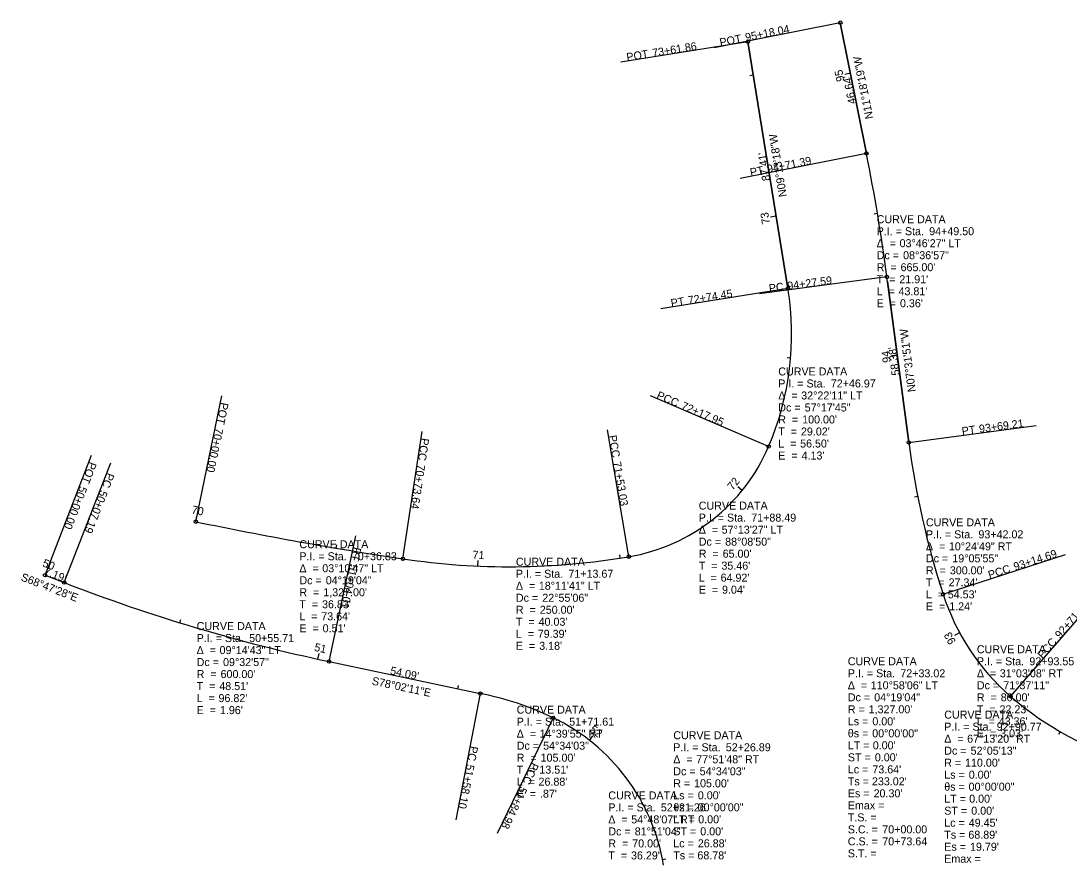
# Model space of a CAD drawing. Extents: x 2047391 to 2047982, y 456752 to 457262.
# Drawn here: x 2047391.4 to 2047758.1, y 456967.1 to 457261.6 of the extents above; entities that cross this region are included whole.
import ezdxf

# ---------------------------------------------------------------- set-up
doc = ezdxf.new("R2010")
doc.units = 0
for name, color, linetype in [('GE_P_Alignment', 7, 'Continuous'), ('GE_P_Alignment_100_Bearings', 7, 'Continuous'), ('GE_P_Alignment_100_Cardinal_Points', 7, 'Continuous'), ('GE_P_Alignment_100_Curve_Data', 7, 'Continuous'), ('GE_P_Alignment_100_Distances', 7, 'Continuous'), ('GE_P_Alignment_100_Stations', 7, 'Continuous')]:
    doc.layers.add(name, color=color, linetype=linetype)

msp = doc.modelspace()

# ---------------------------------------------------------------- linework, layer by layer
at = {"layer": 'GE_P_Alignment'}
for p, q in [((2047678.1, 457261.03), (2047687.24, 457215.29)), ((2047687.24, 457215.29), (2047678.1, 457261.03)), ((2047645.77, 457254.37), (2047659.78, 457168.09)), ((2047659.78, 457168.09), (2047645.77, 457254.37)), ((2047702.06, 457114.21), (2047694.41, 457172.08)), ((2047694.63, 457170.44), (2047702.06, 457114.21)), ((2047399.84, 457067.77), (2047406.55, 457065.16)), ((2047499.24, 457037.56), (2047552.15, 457026.34))]:
    msp.add_line(p, q, dxfattribs=at)
for centre, radius, start, end in [((2047035.15, 457084.92), 665, 7.53092, 11.30514), ((2047035.15, 457084.92), 665, 7.53092, 11.30514), ((2047561.07, 457152.07), 100, 336.8518, 9.2216), ((2047561.07, 457152.07), 100, 336.8518, 9.2216), ((2047593.25, 457138.31), 65, 279.6276, 336.8518), ((2047593.25, 457138.31), 65, 279.6276, 336.8518), ((2047999.47, 457153.53), 300, 187.5309, 197.9445), ((2047999.47, 457153.53), 300, 187.5309, 197.9445), ((2047722.75, 458385.68), 1327, 258.25334, 261.43295), ((2047722.75, 458385.68), 1327, 258.25334, 261.43295), ((2047562.31, 457320.7), 250, 261.433, 279.6276), ((2047562.31, 457320.7), 250, 261.433, 279.6276), ((2047623.61, 457624.52), 600, 248.79098, 258.03635), ((2047790.18, 457085.75), 80, 197.9445, 228.9967), ((2047790.18, 457085.75), 80, 197.9445, 228.9967), ((2047532.02, 456923.29), 105, 64.2811, 78.9463), ((2047809.86, 457108.39), 110, 228.9967, 254.7532), ((2047809.86, 457108.39), 110, 228.9967, 254.7532), ((2047547.24, 456954.81), 70, 9.5095, 64.3115)]:
    msp.add_arc(centre, radius, start, end, dxfattribs=at)
at = {"layer": 'GE_P_Alignment_100_Cardinal_Points'}
for p, q in [((2047678.1, 457261.03), (2047633.97, 457252.2)), ((2047645.77, 457254.37), (2047601.35, 457247.16)), ((2047687.24, 457215.29), (2047643.12, 457206.47)), ((2047694.41, 457172.08), (2047649.8, 457166.18)), ((2047659.78, 457168.09), (2047615.36, 457160.88)), ((2047452.59, 457086.47), (2047461.75, 457130.53)), ((2047653.02, 457112.75), (2047611.64, 457130.44)), ((2047702.06, 457114.21), (2047746.67, 457120.11)), ((2047525.07, 457073.49), (2047531.77, 457117.99)), ((2047604.12, 457074.22), (2047596.6, 457118.59)), ((2047399.84, 457067.77), (2047416.12, 457109.72)), ((2047406.55, 457065.16), (2047422.83, 457107.11)), ((2047499.24, 457037.56), (2047508.56, 457081.58)), ((2047714.07, 457061.1), (2047756.88, 457074.96)), ((2047737.69, 457025.37), (2047767.21, 457059.33)), ((2047552.15, 457026.34), (2047543.52, 456982.18)), ((2047577.59, 457017.89), (2047558.08, 456977.34))]:
    msp.add_line(p, q, dxfattribs=at)
for centre in [(2047678.1, 457261.03), (2047645.77, 457254.37), (2047687.24, 457215.29), (2047694.41, 457172.08), (2047659.78, 457168.09), (2047653.02, 457112.75), (2047702.06, 457114.21), (2047452.59, 457086.47), (2047525.07, 457073.49), (2047604.12, 457074.22), (2047399.84, 457067.77), (2047406.55, 457065.16), (2047714.07, 457061.1), (2047499.24, 457037.56), (2047552.15, 457026.34), (2047737.69, 457025.37), (2047577.59, 457017.89)]:
    msp.add_circle(centre, 0.6, dxfattribs=at)
at = {"layer": 'GE_P_Alignment_100_Stations'}
for p, q in [((2047647.67, 457242.67), (2047646.48, 457242.48)), ((2047681.64, 457243.34), (2047679.67, 457242.95)), ((2047655.68, 457193.31), (2047653.71, 457192.99)), ((2047691.1, 457194.25), (2047689.92, 457194.05)), ((2047660.72, 457143.72), (2047659.52, 457143.82)), ((2047698.03, 457144.73), (2047696.04, 457144.47)), ((2047643.79, 457097.43), (2047642.23, 457098.68)), ((2047705.19, 457095.26), (2047704.01, 457095.02)), ((2047452.59, 457086.47), (2047453, 457088.43)), ((2047501.72, 457077.22), (2047501.92, 457078.4)), ((2047551.29, 457070.94), (2047551.38, 457072.94)), ((2047601.13, 457073.73), (2047600.94, 457074.92)), ((2047399.84, 457067.77), (2047400.56, 457069.63)), ((2047446.97, 457051.11), (2047447.33, 457052.26)), ((2047719.84, 457047.62), (2047718.09, 457046.67)), ((2047495.31, 457038.4), (2047495.74, 457040.35)), ((2047544.23, 457028.02), (2047544.47, 457029.2)), ((2047590.32, 457009.98), (2047591.55, 457011.56)), ((2047755.03, 457013.02), (2047754.44, 457011.98)), ((2047615.93, 456968.27), (2047617.11, 456968.5))]:
    msp.add_line(p, q, dxfattribs=at)

# ---------------------------------------------------------------- texts
at = {"layer": 'GE_P_Alignment_100_Bearings'}
for s, rotation, p in [('N11°18\'19"W', 101.3051, (2047689.68, 457227.61)), ('N09°13\'18"W', 99.2216, (2047659.41, 457200.29)), ('N07°31\'51"W', 97.5309, (2047704.55, 457132.01)), ('S68°47\'28"E', 338.791, (2047391.13, 457066)), ('S78°02\'11"E', 348.0363, (2047514.01, 457029.52))]:
    msp.add_text(s, height=2.8, rotation=rotation, dxfattribs=at).set_placement(p)
at = {"layer": 'GE_P_Alignment_100_Cardinal_Points'}
for s, rotation, p in [('95+18.04', 11.3051, (2047645.12, 457254.48)), ('POT', 11.3051, (2047636.17, 457252.69)), ('73+61.86', 9.2216, (2047612.53, 457249.02)), ('POT', 9.2216, (2047603.52, 457247.56)), ('94+71.39', 11.3051, (2047652.76, 457208.44)), ('PT', 11.3051, (2047646.79, 457207.25)), ('94+27.59', 7.5309, (2047659.77, 457167.55)), ('72+74.45', 9.2216, (2047625.03, 457162.5)), ('PC', 7.5309, (2047653.3, 457166.69)), ('PT', 9.2216, (2047619.02, 457161.52)), ('PCC', 336.8518, (2047613.58, 457129.67)), ('POT', 258.2533, (2047461.35, 457128.36)), ('72+17.95', 336.8518, (2047622.17, 457125.99)), ('PT', 7.5309, (2047720.79, 457116.73)), ('93+69.21', 7.5309, (2047726.82, 457117.53)), ('70+00.00', 258.2533, (2047459.49, 457119.42)), ('PCC', 279.6276, (2047597, 457116.51)), ('PCC', 261.433, (2047531.5, 457115.86)), ('POT', 248.791, (2047415.37, 457107.64)), ('70+73.64', 261.433, (2047530.11, 457106.62)), ('71+53.03', 279.6276, (2047598.56, 457107.29)), ('PC', 248.791, (2047421.59, 457103.8)), ('50+00.00', 248.791, (2047412.06, 457099.13)), ('50+07.19', 248.791, (2047419.23, 457097.72)), ('PT', 258.0363, (2047507.8, 457077.75)), ('93+14.69', 17.9445, (2047739.24, 457069.3)), ('51+04.01', 258.0363, (2047506.54, 457071.8)), ('PCC', 17.9445, (2047730.35, 457066.42)), ('92+71.33', 48.9967, (2047755.01, 457045.37)), ('PCC', 48.9967, (2047748.88, 457038.32)), ('PC', 258.9463, (2047548.65, 457008.17)), ('51+58.10', 258.9463, (2047547.4, 457001.76)), ('PCC', 244.3115, (2047570.21, 457002.46)), ('51+84.98', 244.3115, (2047566.16, 456994.03))]:
    msp.add_text(s, height=2.8, rotation=rotation, dxfattribs=at).set_placement(p)
at = {"layer": 'GE_P_Alignment_100_Curve_Data'}
for s, p in [('CURVE DATA', (2047690.83, 457190.88)), ('P.I. = Sta. ', (2047690.83, 457186.68)), ('94+49.50', (2047709.2, 457186.68)), ('Δ  = ', (2047690.83, 457182.48)), ('03°46\'27" LT', (2047698.85, 457182.48)), ('Dc = ', (2047690.83, 457178.28)), ('08°36\'57"', (2047700.07, 457178.28)), ('R  = ', (2047690.83, 457174.08)), ("665.00'", (2047699.19, 457174.08)), ('T  = ', (2047690.83, 457169.88)), ("21.91'", (2047698.76, 457169.88)), ('L  = ', (2047690.83, 457165.68)), ("43.81'", (2047698.47, 457165.68)), ('E  = ', (2047690.83, 457161.48)), ("0.36'", (2047698.98, 457161.48)), ('CURVE DATA', (2047656.4, 457137.62)), ('P.I. = Sta. ', (2047656.4, 457133.42)), ('72+46.97', (2047674.77, 457133.42)), ('Δ  = ', (2047656.4, 457129.22)), ('32°22\'11" LT', (2047664.42, 457129.22)), ('Dc = ', (2047656.4, 457125.02)), ('57°17\'45"', (2047665.64, 457125.02)), ('R  = ', (2047656.4, 457120.82)), ("100.00'", (2047664.76, 457120.82)), ('T  = ', (2047656.4, 457116.62)), ("29.02'", (2047664.33, 457116.62)), ('L  = ', (2047656.4, 457112.42)), ("56.50'", (2047664.04, 457112.42)), ('E  = ', (2047656.4, 457108.22)), ("4.13'", (2047664.55, 457108.22)), ('CURVE DATA', (2047628.57, 457090.69)), ('P.I. = Sta. ', (2047628.57, 457086.49)), ('71+88.49', (2047646.94, 457086.49)), ('CURVE DATA', (2047708.06, 457084.85)), ('Δ  = ', (2047628.57, 457082.29)), ('57°13\'27" LT', (2047636.59, 457082.29)), ('P.I. = Sta. ', (2047708.06, 457080.65)), ('93+42.02', (2047726.43, 457080.65)), ('CURVE DATA', (2047488.83, 457077.18)), ('Dc = ', (2047628.57, 457078.09)), ('88°08\'50"', (2047637.81, 457078.09)), ('P.I. = Sta. ', (2047488.83, 457072.98)), ('70+36.83', (2047507.2, 457072.98)), ('R  = ', (2047628.57, 457073.89)), ("65.00'", (2047636.94, 457073.89)), ('Δ  = ', (2047708.06, 457076.45)), ('10°24\'49" RT', (2047716.09, 457076.45)), ('CURVE DATA', (2047564.59, 457071.06)), ('T  = ', (2047628.57, 457069.69)), ("35.46'", (2047636.5, 457069.69)), ('Dc = ', (2047708.06, 457072.25)), ('19°05\'55"', (2047717.3, 457072.25)), ('Δ  = ', (2047488.83, 457068.78)), ('03°10\'47" LT', (2047496.85, 457068.78)), ('P.I. = Sta. ', (2047564.59, 457066.86)), ('71+13.67', (2047582.96, 457066.86)), ('R  = ', (2047708.06, 457068.05)), ("300.00'", (2047716.43, 457068.05)), ('Dc = ', (2047488.83, 457064.58)), ('04°19\'04"', (2047498.07, 457064.58)), ('Δ  = ', (2047564.59, 457062.66)), ('18°11\'41" LT', (2047572.62, 457062.66)), ('L  = ', (2047628.57, 457065.49)), ("64.92'", (2047636.22, 457065.49)), ('T  = ', (2047708.06, 457063.85)), ("27.34'", (2047716, 457063.85)), ('R  = ', (2047488.83, 457060.38)), ("1,327.00'", (2047497.2, 457060.38)), ('Dc = ', (2047564.59, 457058.46)), ('22°55\'06"', (2047573.83, 457058.46)), ('E  = ', (2047628.57, 457061.29)), ("9.04'", (2047636.72, 457061.29)), ('L  = ', (2047708.06, 457059.65)), ("54.53'", (2047715.71, 457059.65)), ('T  = ', (2047488.83, 457056.18)), ("36.83'", (2047496.76, 457056.18)), ('E  = ', (2047708.06, 457055.45)), ("1.24'", (2047716.22, 457055.45)), ('L  = ', (2047488.83, 457051.98)), ("73.64'", (2047496.48, 457051.98)), ('R  = ', (2047564.59, 457054.26)), ("250.00'", (2047572.96, 457054.26)), ('CURVE DATA', (2047452.89, 457048.56)), ('E  = ', (2047488.83, 457047.78)), ("0.51'", (2047496.98, 457047.78)), ('T  = ', (2047564.59, 457050.06)), ("40.03'", (2047572.53, 457050.06)), ('P.I. = Sta. ', (2047452.89, 457044.36)), ('50+55.71', (2047471.26, 457044.36)), ('L  = ', (2047564.59, 457045.86)), ("79.39'", (2047572.24, 457045.86)), ('Δ  = ', (2047452.89, 457040.16)), ('09°14\'43" LT', (2047460.91, 457040.16)), ('E  = ', (2047564.59, 457041.66)), ("3.18'", (2047572.75, 457041.66)), ('CURVE DATA', (2047725.88, 457040.44)), ('Dc = ', (2047452.89, 457035.96)), ('09°32\'57"', (2047462.13, 457035.96)), ('CURVE DATA', (2047680.73, 457036.24)), ('P.I. = Sta. ', (2047725.88, 457036.24)), ('92+93.55', (2047744.25, 457036.24)), ('R  = ', (2047452.89, 457031.76)), ("600.00'", (2047461.26, 457031.76)), ('P.I. = Sta. ', (2047680.73, 457032.04)), ('72+33.02', (2047699.1, 457032.04)), ('Δ  = ', (2047725.88, 457032.04)), ('31°03\'08" RT', (2047733.9, 457032.04)), ('T  = ', (2047452.89, 457027.56)), ("48.51'", (2047460.82, 457027.56)), ('Δ  = ', (2047680.73, 457027.84)), ('110°58\'06" LT', (2047688.75, 457027.84)), ('Dc = ', (2047725.88, 457027.84)), ('71°37\'11"', (2047735.12, 457027.84)), ('L  = ', (2047452.89, 457023.36)), ("96.82'", (2047460.54, 457023.36)), ('Dc = ', (2047680.73, 457023.64)), ('04°19\'04"', (2047689.97, 457023.64)), ('R  = ', (2047725.88, 457023.64)), ("80.00'", (2047734.24, 457023.64)), ('E  = ', (2047452.89, 457019.16)), ("1.96'", (2047461.04, 457019.16)), ('CURVE DATA', (2047564.87, 457019.32)), ('R = ', (2047680.73, 457019.44)), ("1,327.00'", (2047688.01, 457019.44)), ('T  = ', (2047725.88, 457019.44)), ("22.23'", (2047733.81, 457019.44)), ('P.I. = Sta. ', (2047564.87, 457015.12)), ('51+71.61', (2047583.24, 457015.12)), ('Ls = ', (2047680.73, 457015.24)), ("0.00'", (2047689.32, 457015.24)), ('CURVE DATA', (2047714.47, 457017.57)), ('L  = ', (2047725.88, 457015.24)), ("43.36'", (2047733.52, 457015.24)), ('Δ  = ', (2047564.87, 457010.92)), ('14°39\'55" RT', (2047572.89, 457010.92)), ('θs = ', (2047680.73, 457011.04)), ('00°00\'00"', (2047689.26, 457011.04)), ('P.I. = Sta. ', (2047714.47, 457013.37)), ('E  = ', (2047725.88, 457011.04)), ('92+90.77', (2047732.83, 457013.37)), ("3.03'", (2047734.03, 457011.04)), ('CURVE DATA', (2047619.66, 457010.36)), ('Δ  = ', (2047714.47, 457009.17)), ('67°13\'20" RT', (2047722.49, 457009.17)), ('Dc = ', (2047564.87, 457006.72)), ('54°34\'03"', (2047574.11, 457006.72)), ('P.I. = Sta. ', (2047619.66, 457006.16)), ('52+26.89', (2047638.03, 457006.16)), ('LT = ', (2047680.73, 457006.84)), ("0.00'", (2047689.46, 457006.84)), ('Dc = ', (2047714.47, 457004.97)), ('52°05\'13"', (2047723.7, 457004.97)), ('R  = ', (2047564.87, 457002.52)), ("105.00'", (2047573.24, 457002.52)), ('Δ  = ', (2047619.66, 457001.96)), ('77°51\'48" RT', (2047627.68, 457001.96)), ('ST = ', (2047680.73, 457002.64)), ("0.00'", (2047690.18, 457002.64)), ('R = ', (2047714.47, 457000.77)), ("110.00'", (2047721.75, 457000.77)), ('T  = ', (2047564.87, 456998.32)), ("13.51'", (2047572.8, 456998.32)), ('Dc = ', (2047619.66, 456997.76)), ('54°34\'03"', (2047628.9, 456997.76)), ('Lc = ', (2047680.73, 456998.44)), ("73.64'", (2047689.32, 456998.44)), ('Ls = ', (2047714.47, 456996.57)), ("0.00'", (2047723.05, 456996.57)), ('L  = ', (2047564.87, 456994.12)), ("26.88'", (2047572.51, 456994.12)), ('R = ', (2047619.66, 456993.56)), ("105.00'", (2047626.94, 456993.56)), ('Ts = ', (2047680.73, 456994.24)), ("233.02'", (2047689.17, 456994.24)), ('θs = ', (2047714.47, 456992.37)), ('00°00\'00"', (2047723, 456992.37)), ('E  = ', (2047564.87, 456989.92)), (".87'", (2047573.02, 456989.92)), ('CURVE DATA', (2047596.93, 456989.33)), ('Ls = ', (2047619.66, 456989.36)), ("0.00'", (2047628.25, 456989.36)), ('Es = ', (2047680.73, 456990.04)), ("20.30'", (2047689.75, 456990.04)), ('P.I. = Sta. ', (2047596.93, 456985.13)), ('52+21.26', (2047615.3, 456985.13)), ('θs = ', (2047619.66, 456985.16)), ('00°00\'00"', (2047628.19, 456985.16)), ('Emax = ', (2047680.73, 456985.84)), ('LT = ', (2047714.47, 456988.17)), ("0.00'", (2047723.2, 456988.17)), ('T.S. = ', (2047680.73, 456981.64)), ('ST = ', (2047714.47, 456983.97)), ("0.00'", (2047723.92, 456983.97)), ('Δ  = ', (2047596.93, 456980.93)), ('54°48\'07" RT', (2047604.95, 456980.93)), ('LT = ', (2047619.66, 456980.96)), ("0.00'", (2047628.39, 456980.96)), ('Lc = ', (2047714.47, 456979.77)), ("49.45'", (2047723.05, 456979.77)), ('Dc = ', (2047596.93, 456976.73)), ('81°51\'04"', (2047606.17, 456976.73)), ('ST = ', (2047619.66, 456976.76)), ("0.00'", (2047629.11, 456976.76)), ('S.C. = ', (2047680.73, 456977.44)), ('70+00.00', (2047692.79, 456977.44)), ('Ts = ', (2047714.47, 456975.57)), ("68.89'", (2047722.91, 456975.57)), ('R  = ', (2047596.93, 456972.53)), ("70.00'", (2047605.3, 456972.53)), ('Lc = ', (2047619.66, 456972.56)), ("26.88'", (2047628.25, 456972.56)), ('C.S. = ', (2047680.73, 456973.24)), ('70+73.64', (2047692.79, 456973.24)), ('Es = ', (2047714.47, 456971.37)), ("19.79'", (2047723.49, 456971.37)), ('T  = ', (2047596.93, 456968.33)), ("36.29'", (2047604.87, 456968.33)), ('Ts = ', (2047619.66, 456968.36)), ("68.78'", (2047628.1, 456968.36)), ('S.T. = ', (2047680.73, 456969.04)), ('Emax = ', (2047714.47, 456967.17))]:
    msp.add_text(s, height=2.8, dxfattribs=at).set_placement(p)
at = {"layer": 'GE_P_Alignment_100_Distances'}
for s, rotation, p in [("46.64'", 101.3051, (2047683.68, 457232.85)), ("87.41'", 99.2216, (2047653.59, 457205.9)), ("58.38'", 97.5309, (2047698.9, 457137.79)), ("7.19'", 338.791, (2047399.19, 457068.07)), ("54.09'", 348.0363, (2047520.42, 457033.11))]:
    msp.add_text(s, height=2.8, rotation=rotation, dxfattribs=at).set_placement(p)
at = {"layer": 'GE_P_Alignment_100_Stations'}
for s, rotation, p in [('95', 101.3051, (2047679.57, 457240.68)), ('73', 99.2216, (2047653.52, 457190.76)), ('94', 97.5309, (2047695.78, 457142.27)), ('72', 51.03, (2047640.47, 457097.3)), ('70', 348.2533, (2047450.96, 457089.41)), ('71', 357.4739, (2047549.38, 457073.53)), ('50', 338.791, (2047398.72, 457070.93)), ('93', 118.4622, (2047718.64, 457044.49)), ('51', 347.6533, (2047493.88, 457041.32)), ('52', 322.0155, (2047590.17, 457013.33))]:
    msp.add_text(s, height=2.8, rotation=rotation, dxfattribs=at).set_placement(p)

doc.saveas('drawing.dxf')
